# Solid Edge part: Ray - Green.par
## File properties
Author: hhakima
Template: Normal.par
Last saved by: hhakima
Revision: 15
Application: Solid Edge
Accuracy: 0.990
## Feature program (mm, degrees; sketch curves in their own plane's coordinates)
sketch for "unnamed Protrusion 1" plane through (0, 0, 0) normal (0, -1, 0) x-axis (1, 0, 0)
  circle centre (0, 0) radius 1.2
extrude "unnamed Protrusion 1" add finite 10.6 along -normal
sketch for "ExtrudedProtrusion_2" plane through (0, 0, 1.2) normal (1, 0, 0) x-axis (0, 1, 0)
extrude "ExtrudedProtrusion_2" add finite 120 along +normal
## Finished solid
Body 1: solid body, 7 faces, 10 edges, 5 vertices.
  Faces by surface: plane 5, cylinder 2
  Edges by curve: circle 5, intersection 3, line 2
Bounding box of the edges (mm): 121.200 x 10.600 x 2.500, from (-1.2, 0, -1.25) to (120, 10.6, 1.25).
Cylindrical faces by radius (mm): R1.2 x1, R1.25 x1
Planar faces by outward normal: +x 1, +y 1, -x 2, -y 1
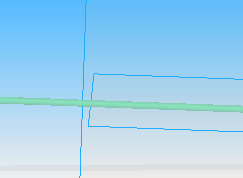
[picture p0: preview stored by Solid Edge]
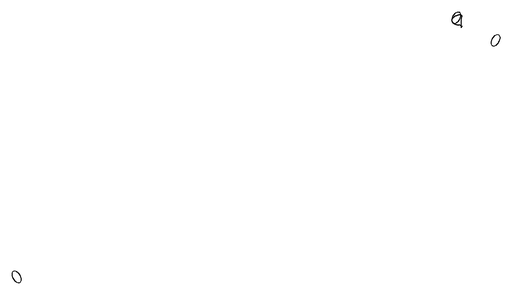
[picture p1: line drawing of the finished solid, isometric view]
